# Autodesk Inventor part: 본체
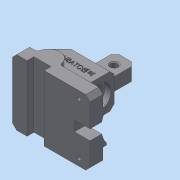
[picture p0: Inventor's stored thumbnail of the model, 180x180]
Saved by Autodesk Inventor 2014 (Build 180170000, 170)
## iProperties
Created: 2022-08
Part Number: 본체
Material: 일반
Document SubType Name: Modeling
Designer: dg
Density: 1 g/cm^3
Appearance: 기본값
Author: dg
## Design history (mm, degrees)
sketch "스케치1"
  geometry: L1 (-45, 0)-(45, 0); L2 (-45, 0)-(-45, 42); L3 (-45, 42)-(-27, 60); L4 (-27, 60)-(13, 60); L5 (13, 60)-(13, 19); L6 (13, 19)-(45, 19); L7 (45, 19)-(45, 0); 2 further points
  constraints: 14 end point, 3 parallel, 2 perpendicular, 1 coincident, 1 horizontal, 1 horizontal alignment, 1 midpoint
  dimensions: "d0" = 90 distance of L1.start L1.end; "d2" = 19 distance of L6.end L1.end; "d3" = 32 distance of L5.end L6.end; "d4" = 45 deg angle of L3 L4; "d5" = 18 horizontal distance of L3.end L2.end; "d8" = 60 distance between parallel lines of L1 L4
extrude "돌출1" new body sketch "스케치1" stored distance "d6" = 40; taper "d7" = 0 deg
node "작업 평면1"
sketch "스케치2"
  geometry: L1 (-45, 0)-(-45, 42) reference; L2 (13, 60)-(13, 19) reference; L3 (-45, 42)-(13, 42); L4 (45, 0)-(-45, 0) reference; L5 (13, 56.5)-(6, 56.5); L6 (6, 56.5)-(6, 52); L7 (-45, 42)-(-27, 60) reference; L8 (6, 52)-(-45, 52); L9 (-45, 52)-(-45, 42); 1 further point
  constraints: 10 end point, 4 perpendicular, 3 point on line, 1 parallel
  dimensions: "d9" = 42 distance between parallel lines of L4 L3; "d10" = 20 diameter of L8 L3; "d11" = 29 diameter of L5 L3; "d12" = 7 distance of L5.start L5.end
revolve "회전1" sketch "스케치2" stored, may be unused: angle "d13" = 90 deg
node "작업 평면2"
sketch "스케치3"
  geometry: L1 (-27, 60)-(13, 60) reference; L2 (-16, 60)-(-16, 90); L3 (-16, 90)-(8, 90); L4 (8, 90)-(8, 60); L5 (13, 56.5)-(13, 27.5) reference; 1 further point
  constraints: 6 end point, 3 perpendicular, 2 point on line
  dimensions: "d14" = 24 distance of L2.end L3.end; "d15" = 5 distance between parallel lines of L5 L4; "d16" = 30 distance of L2.start L2.end
extrude "돌출2" join sketch "스케치3" stored distance "d17" = 15; taper "d18" = 0 deg
chamfer "모따기1" distance "d19" = 5; stored, may be unused: second distance "d20" = 2, angle "d21" = 45 deg
sketch "스케치4"
  geometry: L1 (8, 60)-(8, 85) reference; L2 (-45, 0)-(45, 0) reference; C1 r 4 at (-4, 77); 1 further point
  constraints: 1 centre point
  dimensions: "d22" = 12 distance from line of L1 C1.centre; "d23" = 77 distance from line of L2 C1.centre; "d24" = 8 diameter of C1
extrude "돌출3" cut sketch "스케치4" distance "d25" = 15; taper "d26" = 0 deg
chamfer "모따기2" distance "d27" = 1; stored, may be unused: second distance "d28" = 2, angle "d29" = 45 deg
chamfer "모따기3" distance "d30" = 5; stored, may be unused: second distance "d31" = 2, angle "d32" = 45 deg
chamfer "모따기4" distance "d33" = 1; stored, may be unused: second distance "d34" = 2, angle "d35" = 45 deg
sketch "스케치5"
  geometry: L1 (-45, 42)-(-45, 0) reference; L2 (-45, 0)-(45, 0) reference; L3 (45, 0)-(45, 19) reference; L4 (13, 19)-(13, 55) reference; L5 (45, 15)-(-5, 15); L6 (-31, 15)-(-45, 15); A1 r 13 centre (-18, 15) between (-5, 15) and (-31, 15); 1 further point
  constraints: 4 end point, 3 point on line, 2 perpendicular, 2 point on circle, 1 centre point, 1 horizontal alignment
  dimensions: "d36" = 15 distance between parallel lines of L2 L6; "d37" = 13 radius of A1; "d38" = 27 distance from line of L1 A1.centre
extrude "돌출4" join sketch "스케치5" distance "d39" = 18; taper "d40" = 0 deg
chamfer "모따기5" distance "d41" = 5; stored, may be unused: second distance "d42" = 2, angle "d43" = 45 deg
chamfer "모따기6" distance "d44" = 5; stored, may be unused: second distance "d45" = 2, angle "d46" = 45 deg
node "작업 평면3"
chamfer "모따기7" distance "d47" = 5; stored, may be unused: second distance "d48" = 2, angle "d49" = 45 deg
sketch "스케치6"
  geometry: L1 (-40, 0)-(40, 0) reference; L2 (-28, 0)-(-28, 8); L3 (-28, 8)-(-8, 8); L4 (-8, 8)-(-8, 0); A1 r 13 centre (-18, 15) between (-5, 15) and (-31, 15) reference; 1 further point
  constraints: 6 end point, 3 perpendicular, 2 point on line
  dimensions: "d50" = 20 distance between parallel lines of L4 L2; "d51" = 10 distance from line of A1.centre L2; "d52" = 8 distance between parallel lines of L1 L3
extrude "돌출5" cut sketch "스케치6" stored distance "d53" = 18; taper "d54" = 0 deg
sketch "스케치7"
  geometry: L1 (40, 0)-(0, 0) reference; L2 (53, -19)-(-13, -19) reference; L3 (14, -19)-(14, -5.373); L4 (26, -19)-(26, -5.373); C1 r 14.5 at (20, 23) reference; A1 r 29 centre (20, 23) between (2.336, 0) and (14, -5.373); A2 r 29 centre (20, 23) between (26, -5.373) and (37.664, 0); 1 further point
  constraints: 4 end point, 4 point on circle, 4 point on line, 3 concentric, 2 centre point, 1 parallel, 1 perpendicular
  dimensions: "d55" = 12 distance between parallel lines of L4 L3; "d56" = 6 distance from line of point (20, -19) L3; "d57" = 29 radius of A1
extrude "돌출6" cut sketch "스케치7" distance "d58" = 18; taper "d59" = 0 deg
sketch "스케치8"
  geometry: L1 (50, 0)-(50, -13) reference; L2 (68, 20)-(-58, 20) reference; L3 (32, 2.336)-(32, 37.664) reference; 2 further points
  dimensions: "d60" = 13 distance from line of L1 point (37, -10); "d61" = 30 distance from line of point (37, -10) L2
hole "구멍1" sketch "스케치8" at (37, -10) diameter "d62" = 4.5; stored, may be unused: countersink angle "d66" = 90 deg, drill point angle "d68" = 118 deg; dims "d63" = 6, "d64" = 8, "d65" = 4.4, "d67" = 8
node "작업 평면4"
fillet "모깎기1" dims "d69" = 3
fillet "모깎기2" dims "d70" = 3
sketch "스케치9"
  geometry: L1 (13, 22)-(13, 55) reference; L2 (13, 60)-(-27, 60) reference; 2 further points
  constraints: 1 other
  dimensions: "d71" = 26 distance from line of L1 point (-13, 42); "d72" = 18 distance from line of L2 point (-13, 42)
feature "엠보싱1" sketch "스케치9" dims "d9" = 42, "d10" = 20, "d11" = 29, "d12" = 7, "d73" = 0.5, "d74" = 0
node "솔리드1"
mirror "대칭1"
mirror "대칭2"
